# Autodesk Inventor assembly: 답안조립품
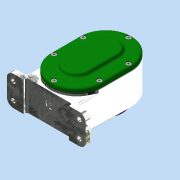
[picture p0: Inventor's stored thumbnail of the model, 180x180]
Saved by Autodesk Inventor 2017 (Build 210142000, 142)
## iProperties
Part Number: 답안조립품
Material: 일반
Document SubType Name: Assembly
Designer: MRC
Author: MRC
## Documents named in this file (19)
- C:\Users\MRC\Desktop\710609V1011\답안조립품.iam
- C:\Users\MRC\Desktop\710609V1011\본체.ipt
- C:\Users\MRC\Desktop\710609V1011\개스킷 A.ipt
- C:\Users\MRC\Desktop\710609V1011\개스킷 B.ipt
- C:\Users\MRC\Desktop\710609V1011\베어링 6001.ipt
- 베어링 6001.ipt
- C:\Users\MRC\Desktop\710609V1011\베어링 6002.ipt
- 베어링 6002.ipt
- C:\Users\MRC\Desktop\710609V1011\볼트 M4.ipt
- C:\Users\MRC\Desktop\710609V1011\스퍼기어 A.ipt
- C:\Users\MRC\Desktop\710609V1011\스퍼기어 B.ipt
- C:\Users\MRC\Desktop\710609V1011\오일 실 12 22 7.ipt
- C:\Users\MRC\Desktop\710609V1011\축 A.ipt
- C:\Users\MRC\Desktop\710609V1011\축 B.ipt
- C:\Users\MRC\Desktop\710609V1011\칼라.ipt
- C:\Users\MRC\Desktop\710609V1011\커버 A.ipt
- C:\Users\MRC\Desktop\710609V1011\커버 B.ipt
- C:\Users\MRC\Desktop\710609V1011\키 4 x 4 x 12.ipt
- C:\Users\MRC\Desktop\710609V1011\키 5 x 5 x 12.ipt
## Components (2 placed, 2 different names)
1. 개스킷 A:1
2. 개스킷 B:1
